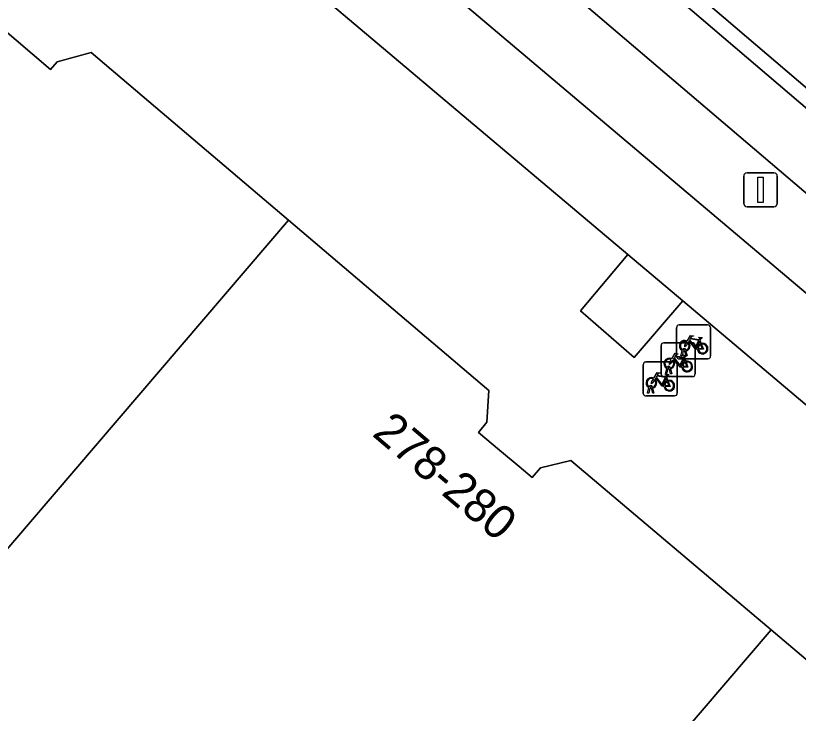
# Model space of a CAD drawing. Extents: x 162344 to 162869, y 381217 to 381818.
# Drawn here: x 162714.57 to 162737.65, y 381610.04 to 381630.62 of the extents above; entities that cross this region are included whole.
import ezdxf

# ---------------------------------------------------------------- set-up
doc = ezdxf.new("R2010")
doc.units = 0
for name, color, linetype in [('IMGEO_Berm_open', 7, 'Continuous'), ('IMGEO_Fietsenrek', 7, 'Continuous'), ('IMGEO_Fietspad_gesloten', 7, 'Continuous'), ('IMGEO_Groenvoorziening', 7, 'Continuous'), ('IMGEO_Lichtmast', 7, 'Continuous'), ('IMGEO_Pand', 7, 'Continuous'), ('IMGEO_Pand_nummerreeks', 7, 'Continuous'), ('IMGEO_Parkeervlak_open', 7, 'Continuous'), ('IMGEO_Rijbaan_lokaal_gesloten', 7, 'Continuous'), ('IMGEO_Rijbaan_lokaal_open', 7, 'Continuous'), ('IMGEO_Voetpad_open', 7, 'Continuous')]:
    doc.layers.add(name, color=color, linetype=linetype)

msp = doc.modelspace()

# ---------------------------------------------------------------- linework, layer by layer
at = {"layer": 'IMGEO_Berm_open'}
for points in [[(162696.427, 381662.56), (162694.013, 381659.509), (162702.028, 381652.737), (162703.396, 381654.339), (162706.444, 381651.742), (162705.095, 381650.146), (162708.354, 381647.393), (162719.685, 381637.816), (162720.913, 381639.242), (162724.107, 381636.516), (162722.898, 381635.101), (162740.536, 381620.194), (162741.701, 381621.535), (162744.891, 381618.803), (162743.753, 381617.476), (162759.809, 381603.905), (162760.883, 381605.14), (162764.076, 381602.441), (162763.006, 381601.204), (162768.998, 381596.139), (162779.07, 381587.644)], [(162759.969, 381606.584), (162761.128, 381608.048), (162761.412, 381608.404), (162754.725, 381614.122), (162754.407, 381613.79), (162753.144, 381612.386), (162716.734, 381643.412), (162718.101, 381644.792), (162718.383, 381645.147), (162700.335, 381660.484)]]:
    msp.add_lwpolyline(points, dxfattribs=at)
at = {"layer": 'IMGEO_Fietsenrek'}
for p, q in [((162734.059, 381620.572), (162734.059, 381621.413)), ((162734.059, 381621.413), (162734.059, 381620.572)), ((162734.134, 381621.497), (162734.975, 381621.497)), ((162734.975, 381621.497), (162734.134, 381621.497)), ((162735.059, 381621.422), (162735.059, 381620.581)), ((162735.059, 381620.581), (162735.059, 381621.422)), ((162733.605, 381620.047), (162733.605, 381620.888)), ((162733.605, 381620.888), (162733.605, 381620.047)), ((162733.68, 381620.972), (162734.521, 381620.972)), ((162734.521, 381620.972), (162733.68, 381620.972)), ((162734.605, 381620.897), (162734.605, 381620.056)), ((162734.605, 381620.056), (162734.605, 381620.897)), ((162734.746, 381621.046), (162734.782, 381620.951)), ((162734.186, 381620.581), (162734.225, 381620.741)), ((162734.255, 381620.729), (162734.22, 381620.581)), ((162734.297, 381620.753), (162734.296, 381620.757)), ((162734.338, 381620.581), (162734.304, 381620.723)), ((162734.328, 381620.764), (162734.329, 381620.757)), ((162734.336, 381620.727), (162734.371, 381620.581)), ((162734.984, 381620.497), (162734.143, 381620.497)), ((162734.143, 381620.497), (162734.984, 381620.497)), ((162734.22, 381620.581), (162734.186, 381620.581)), ((162734.292, 381620.521), (162734.328, 381620.426)), ((162734.371, 381620.581), (162734.338, 381620.581)), ((162733.076, 381619.479), (162733.076, 381620.32)), ((162733.076, 381620.32), (162733.076, 381619.479)), ((162733.151, 381620.404), (162733.992, 381620.404)), ((162733.992, 381620.404), (162733.151, 381620.404)), ((162733.732, 381620.056), (162733.771, 381620.216)), ((162733.801, 381620.204), (162733.766, 381620.056)), ((162733.843, 381620.228), (162733.842, 381620.232)), ((162733.884, 381620.056), (162733.85, 381620.198)), ((162733.874, 381620.239), (162733.875, 381620.232)), ((162733.882, 381620.202), (162733.917, 381620.056)), ((162734.076, 381620.329), (162734.076, 381619.488)), ((162734.076, 381619.488), (162734.076, 381620.329)), ((162734.53, 381619.972), (162733.689, 381619.972)), ((162733.689, 381619.972), (162734.53, 381619.972)), ((162733.766, 381620.056), (162733.732, 381620.056)), ((162733.917, 381620.056), (162733.884, 381620.056)), ((162733.763, 381619.953), (162733.799, 381619.858)), ((162733.203, 381619.488), (162733.242, 381619.648)), ((162733.272, 381619.636), (162733.237, 381619.488)), ((162733.314, 381619.66), (162733.313, 381619.664)), ((162733.355, 381619.488), (162733.321, 381619.63)), ((162733.345, 381619.671), (162733.346, 381619.664)), ((162733.353, 381619.634), (162733.388, 381619.488)), ((162734.001, 381619.404), (162733.16, 381619.404)), ((162733.16, 381619.404), (162734.001, 381619.404)), ((162733.237, 381619.488), (162733.203, 381619.488)), ((162733.388, 381619.488), (162733.355, 381619.488))]:
    msp.add_line(p, q, dxfattribs=at)
for points in [[(162734.372, 381621.023), (162734.467, 381621.187), (162734.553, 381621.173), (162734.555, 381621.164), (162734.499, 381621.153), (162734.472, 381621.108), (162734.728, 381621.067)], [(162734.728, 381621.067), (162734.753, 381621.116), (162734.747, 381621.12), (162734.724, 381621.124), (162734.712, 381621.131), (162734.711, 381621.134), (162734.713, 381621.139), (162734.808, 381621.124), (162734.81, 381621.114), (162734.8, 381621.101), (162734.788, 381621.095), (162734.774, 381621.101), (162734.746, 381621.046)], [(162734.393, 381620.971), (162734.341, 381620.881), (162734.301, 381620.856), (162734.302, 381620.903), (162734.357, 381620.997)], [(162734.668, 381620.779), (162734.618, 381620.779), (162734.427, 381621.03), (162734.408, 381620.998)], [(162734.715, 381621.042), (162734.458, 381621.083), (162734.441, 381621.054), (162734.608, 381620.834), (162734.715, 381621.042)], [(162734.763, 381620.944), (162734.733, 381621.021), (162734.624, 381620.803), (162734.667, 381620.803)], [(162734.697, 381620.803), (162734.817, 381620.802), (162734.773, 381620.916)], [(162734.793, 381620.923), (162734.848, 381620.778), (162734.698, 381620.778)], [(162733.918, 381620.498), (162734.013, 381620.662), (162734.099, 381620.648), (162734.101, 381620.639), (162734.045, 381620.628), (162734.018, 381620.583), (162734.274, 381620.542)], [(162733.939, 381620.446), (162733.887, 381620.356), (162733.847, 381620.331), (162733.848, 381620.378), (162733.903, 381620.472)], [(162734.214, 381620.254), (162734.164, 381620.254), (162733.973, 381620.505), (162733.954, 381620.473)], [(162734.261, 381620.517), (162734.004, 381620.558), (162733.987, 381620.529), (162734.154, 381620.309), (162734.261, 381620.517)], [(162734.309, 381620.419), (162734.279, 381620.496), (162734.17, 381620.278), (162734.213, 381620.278)], [(162734.274, 381620.542), (162734.299, 381620.591), (162734.293, 381620.595), (162734.27, 381620.599), (162734.258, 381620.606), (162734.257, 381620.609), (162734.259, 381620.614), (162734.354, 381620.599), (162734.356, 381620.589), (162734.346, 381620.576), (162734.334, 381620.57), (162734.32, 381620.576), (162734.292, 381620.521)], [(162734.243, 381620.278), (162734.363, 381620.277), (162734.319, 381620.391)], [(162734.339, 381620.398), (162734.394, 381620.253), (162734.244, 381620.253)], [(162733.389, 381619.93), (162733.484, 381620.094), (162733.57, 381620.08), (162733.572, 381620.071), (162733.516, 381620.06), (162733.489, 381620.015), (162733.745, 381619.974)], [(162733.732, 381619.949), (162733.475, 381619.99), (162733.458, 381619.961), (162733.625, 381619.741), (162733.732, 381619.949)], [(162733.745, 381619.974), (162733.77, 381620.023), (162733.764, 381620.027), (162733.741, 381620.031), (162733.729, 381620.038), (162733.728, 381620.041), (162733.73, 381620.046), (162733.825, 381620.031), (162733.827, 381620.021), (162733.817, 381620.008), (162733.805, 381620.002), (162733.791, 381620.008), (162733.763, 381619.953)], [(162733.41, 381619.878), (162733.358, 381619.788), (162733.318, 381619.763), (162733.319, 381619.81), (162733.374, 381619.904)], [(162733.685, 381619.686), (162733.635, 381619.686), (162733.444, 381619.937), (162733.425, 381619.905)], [(162733.78, 381619.851), (162733.75, 381619.928), (162733.641, 381619.71), (162733.684, 381619.71)], [(162733.714, 381619.71), (162733.834, 381619.709), (162733.79, 381619.823)], [(162733.81, 381619.83), (162733.865, 381619.685), (162733.715, 381619.685)]]:
    msp.add_lwpolyline(points, dxfattribs=at)
for centre, radius, start, end in [((162734.137, 381621.419), 0.0779, 92.4484, 184.2845), ((162734.137, 381621.419), 0.0779, 92.4484, 184.2845), ((162734.981, 381621.419), 0.0779, 2.4484, 94.2845), ((162734.981, 381621.419), 0.0779, 2.4484, 94.2845), ((162733.683, 381620.894), 0.0779, 92.4484, 184.2845), ((162733.683, 381620.894), 0.0779, 92.4484, 184.2845), ((162734.299, 381620.882), 0.159, 62.6766, 242.1369), ((162734.299, 381620.882), 0.129, 63.3192, 238.903), ((162734.299, 381620.882), 0.129, 283.6043, 43.4302), ((162734.299, 381620.882), 0.159, 283.5766, 46.6042), ((162734.527, 381620.894), 0.0779, 2.4484, 94.2845), ((162734.527, 381620.894), 0.0779, 2.4484, 94.2845), ((162734.826, 381620.798), 0.159, 113.3408, 178.3217), ((162734.826, 381620.798), 0.159, 187.0065, 105.7708), ((162734.826, 381620.798), 0.129, 113.923, 177.9556), ((162734.826, 381620.798), 0.129, 188.6715, 104.5883), ((162734.279, 381620.753), 0.0499, 12.8025, 158.6934), ((162734.299, 381620.882), 0.159, 253.9967, 271.7867), ((162734.279, 381620.753), 0.0174, 12.8025, 163.4502), ((162734.299, 381620.882), 0.129, 253.415, 269.0204), ((162733.845, 381620.357), 0.159, 62.6766, 242.1369), ((162733.845, 381620.357), 0.129, 63.3192, 238.903), ((162733.845, 381620.357), 0.129, 283.6043, 43.4302), ((162733.845, 381620.357), 0.159, 283.5766, 46.6042), ((162734.137, 381620.575), 0.0779, 182.4484, 274.2845), ((162734.137, 381620.575), 0.0779, 182.4484, 274.2845), ((162734.372, 381620.273), 0.159, 187.0065, 105.7708), ((162734.981, 381620.575), 0.0779, 272.4484, 4.2845), ((162734.981, 381620.575), 0.0779, 272.4484, 4.2845), ((162733.154, 381620.326), 0.0779, 92.4484, 184.2845), ((162733.154, 381620.326), 0.0779, 92.4484, 184.2845), ((162733.825, 381620.228), 0.0499, 12.8025, 158.6934), ((162733.845, 381620.357), 0.159, 253.9967, 271.7867), ((162733.825, 381620.228), 0.0174, 12.8025, 163.4502), ((162733.845, 381620.357), 0.129, 253.415, 269.0204), ((162733.998, 381620.326), 0.0779, 2.4484, 94.2845), ((162733.998, 381620.326), 0.0779, 2.4484, 94.2845), ((162734.372, 381620.273), 0.159, 113.3408, 178.3217), ((162734.372, 381620.273), 0.129, 113.923, 177.9556), ((162734.372, 381620.273), 0.129, 188.6715, 104.5883), ((162733.683, 381620.05), 0.0779, 182.4484, 274.2845), ((162733.683, 381620.05), 0.0779, 182.4484, 274.2845), ((162734.527, 381620.05), 0.0779, 272.4484, 4.2845), ((162734.527, 381620.05), 0.0779, 272.4484, 4.2845), ((162733.316, 381619.789), 0.159, 62.6766, 242.1369), ((162733.316, 381619.789), 0.129, 63.3192, 238.903), ((162733.316, 381619.789), 0.129, 283.6043, 43.4302), ((162733.316, 381619.789), 0.159, 283.5766, 46.6042), ((162733.843, 381619.705), 0.159, 113.3408, 178.3217), ((162733.843, 381619.705), 0.159, 187.0065, 105.7708), ((162733.843, 381619.705), 0.129, 113.923, 177.9556), ((162733.843, 381619.705), 0.129, 188.6715, 104.5883), ((162733.296, 381619.66), 0.0499, 12.8025, 158.6934), ((162733.316, 381619.789), 0.159, 253.9967, 271.7867), ((162733.296, 381619.66), 0.0174, 12.8025, 163.4502), ((162733.316, 381619.789), 0.129, 253.415, 269.0204), ((162733.154, 381619.482), 0.0779, 182.4484, 274.2845), ((162733.154, 381619.482), 0.0779, 182.4484, 274.2845), ((162733.998, 381619.482), 0.0779, 272.4484, 4.2845), ((162733.998, 381619.482), 0.0779, 272.4484, 4.2845)]:
    msp.add_arc(centre, radius, start, end, dxfattribs=at)
at = {"layer": 'IMGEO_Fietspad_gesloten'}
for points in [[(162684.232, 381664.825), (162688.355, 381661.085), (162692.352, 381657.601), (162694.144, 381656.087), (162695.755, 381654.725), (162704.011, 381647.75), (162705.608, 381646.401), (162718.443, 381635.556), (162720.034, 381634.212), (162732.624, 381623.574), (162734.239, 381622.209), (162743.076, 381614.743), (162746.831, 381611.57), (162748.438, 381610.212), (162761.023, 381599.578), (162762.605, 381598.241), (162775.215, 381587.585), (162776.8, 381586.246), (162789.414, 381575.587), (162791.002, 381574.245), (162797.286, 381568.935), (162800.436, 381566.273), (162829.055, 381542.09), (162840.499, 381532.368)], [(162841.502, 381534.811), (162837.376, 381538.357), (162836.448, 381539.154), (162830.443, 381544.315), (162820.68, 381552.549), (162817.483, 381555.246), (162799.811, 381570.151), (162796.513, 381572.933), (162782.289, 381584.929), (162779.07, 381587.644), (162768.998, 381596.139), (162763.006, 381601.204), (162759.809, 381603.905), (162743.753, 381617.476), (162740.536, 381620.194), (162722.898, 381635.101), (162719.685, 381637.816), (162708.354, 381647.393), (162705.095, 381650.146), (162702.028, 381652.737), (162694.013, 381659.509), (162690.775, 381662.288)]]:
    msp.add_lwpolyline(points, dxfattribs=at)
at = {"layer": 'IMGEO_Groenvoorziening'}
msp.add_lwpolyline([(162734.239, 381622.209), (162732.624, 381623.574), (162731.227, 381621.914), (162732.804, 381620.54)], close=True, dxfattribs=at)
at = {"layer": 'IMGEO_Lichtmast'}
for p, q in [((162736.138, 381625.985), (162736.928, 381625.985)), ((162736.928, 381625.985), (162736.138, 381625.985)), ((162736.038, 381625.085), (162736.038, 381625.885)), ((162736.038, 381625.885), (162736.038, 381625.085)), ((162737.028, 381625.885), (162737.028, 381625.085)), ((162737.028, 381625.085), (162737.028, 381625.885)), ((162736.928, 381624.985), (162736.138, 381624.985)), ((162736.138, 381624.985), (162736.928, 381624.985))]:
    msp.add_line(p, q, dxfattribs=at)
msp.add_lwpolyline([(162736.458, 381625.86), (162736.608, 381625.86), (162736.608, 381625.11), (162736.458, 381625.11), (162736.458, 381625.86)], dxfattribs=at)
for centre, start, end in [((162736.138, 381625.885), 90, 180), ((162736.138, 381625.885), 90, 180), ((162736.928, 381625.885), 0, 90), ((162736.928, 381625.885), 360, 90), ((162736.138, 381625.085), 180, 270), ((162736.138, 381625.085), 180, 270), ((162736.928, 381625.085), 270, 0), ((162736.928, 381625.085), 270, 0)]:
    msp.add_arc(centre, 0.1, start, end, dxfattribs=at)
at = {"layer": 'IMGEO_Pand'}
for points in [[(162722.614, 381624.591), (162716.804, 381629.538), (162715.798, 381629.263), (162715.605, 381629.033), (162714.036, 381630.358), (162714.245, 381630.614), (162714.347, 381631.615), (162708.391, 381636.674), (162697.07, 381623.436), (162711.285, 381611.345)], [(162736.849, 381612.501), (162730.942, 381617.502), (162730.049, 381617.281), (162729.803, 381616.992), (162729.413, 381617.32), (162728.841, 381617.803), (162728.221, 381618.325), (162728.46, 381618.633), (162728.523, 381619.56), (162722.614, 381624.591), (162711.285, 381611.345), (162715.977, 381607.354), (162725.513, 381599.243)], [(162750.894, 381600.568), (162745.129, 381605.46), (162744.187, 381605.228), (162743.961, 381604.974), (162742.402, 381606.301), (162742.611, 381606.552), (162742.724, 381607.528), (162736.849, 381612.501), (162725.513, 381599.243), (162739.55, 381587.303)]]:
    msp.add_lwpolyline(points, close=True, dxfattribs=at)
at = {"layer": 'IMGEO_Parkeervlak_open'}
msp.add_lwpolyline([(162718.101, 381644.792), (162716.734, 381643.412), (162753.144, 381612.386), (162754.407, 381613.79)], close=True, dxfattribs=at)
at = {"layer": 'IMGEO_Rijbaan_lokaal_gesloten'}
msp.add_lwpolyline([(162700.335, 381660.484), (162718.383, 381645.147), (162754.725, 381614.122), (162761.412, 381608.404), (162802.506, 381573.344), (162829.77, 381550.157), (162832.081, 381548.137)], dxfattribs=at)
at = {"layer": 'IMGEO_Rijbaan_lokaal_open'}
msp.add_lwpolyline([(162718.383, 381645.147), (162718.101, 381644.792), (162754.407, 381613.79), (162754.725, 381614.122)], close=True, dxfattribs=at)
at = {"layer": 'IMGEO_Voetpad_open'}
for points in [[(162743.076, 381614.743), (162734.239, 381622.209), (162732.804, 381620.54), (162731.227, 381621.914), (162732.624, 381623.574), (162720.034, 381634.212), (162718.579, 381632.553), (162717.016, 381633.887), (162718.443, 381635.556), (162705.608, 381646.401), (162704.2, 381644.736), (162702.594, 381646.082), (162704.011, 381647.75), (162695.755, 381654.725), (162694.259, 381653.034), (162692.702, 381654.405), (162694.144, 381656.087), (162692.352, 381657.601), (162688.355, 381661.085), (162685.311, 381658.19)], [(162714.036, 381630.358), (162715.605, 381629.033), (162715.798, 381629.263), (162716.804, 381629.538), (162722.614, 381624.591), (162728.523, 381619.56), (162728.46, 381618.633), (162728.221, 381618.325), (162728.841, 381617.803), (162729.413, 381617.32), (162729.803, 381616.992), (162730.049, 381617.281), (162730.942, 381617.502), (162736.849, 381612.501), (162742.724, 381607.528)]]:
    msp.add_lwpolyline(points, dxfattribs=at)

# ---------------------------------------------------------------- texts
at = {"layer": 'IMGEO_Pand_nummerreeks'}
msp.add_text('278-280', height=1, rotation=319.6924, dxfattribs=at).set_placement((162725.053, 381618.249))

doc.saveas('drawing.dxf')
